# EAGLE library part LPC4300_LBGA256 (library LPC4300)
LBGA256 - SOT740-2 LBGA256: plastic low profile ball grid array package; 256 balls grid 1 * 1 mm; body 17 * 17 mm; Solderland 0.45 mm diameter
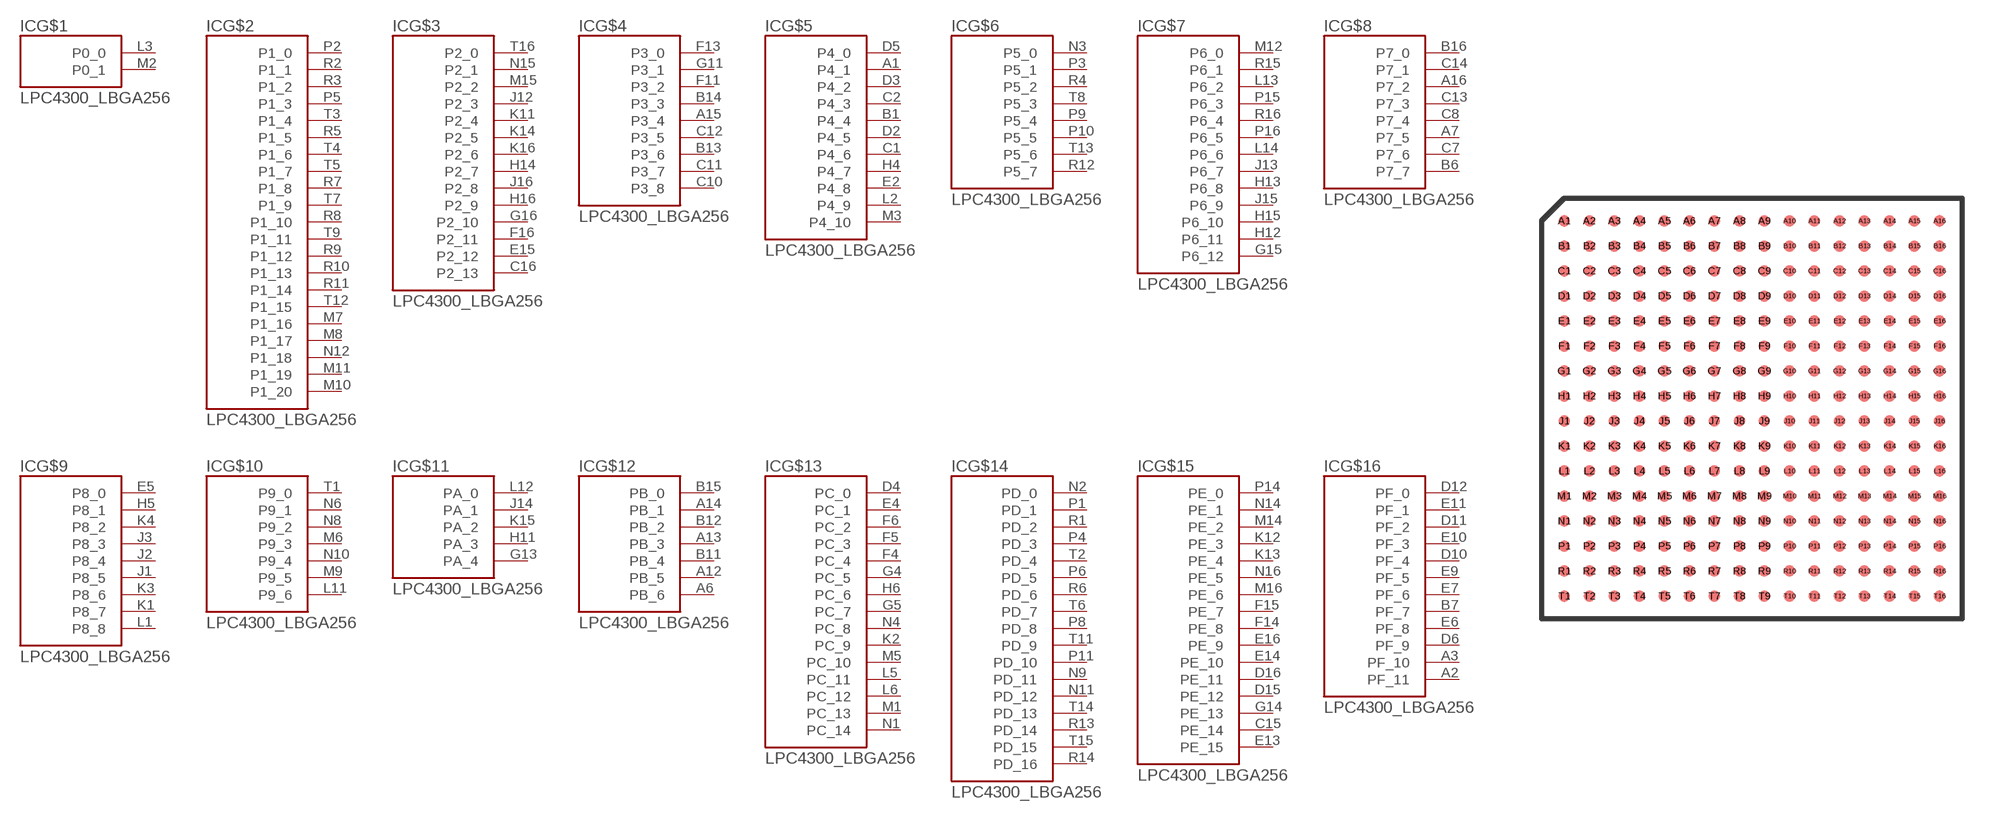
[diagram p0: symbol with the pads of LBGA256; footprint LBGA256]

Designator prefix IC; gates G$1=LPC4300_0_PORT0 G$2=LPC4300_1_PORT1 G$3=LPC4300_2_PORT2 G$4=LPC4300_3_PORT3 G$5=LPC4300_4_PORT4 G$6=LPC4300_5_PORT5 G$7=LPC4300_6_PORT6 G$8=LPC4300_7_PORT7 G$9=LPC4300_8_PORT8 G$10=LPC4300_9_PORT9 G$11=LPC4300_10_PORTA G$12=LPC4300_11_PORTB G$13=LPC4300_12_PORTC G$14=LPC4300_13_PORTD G$15=LPC4300_14_PORTE G$16=LPC4300_15_PORTF G$17=LPC4300_16_ANA G$18=LPC4300_17_RTC G$19=LPC4300_18_CLK G$20=LPC4300_19_DBUG G$21=LPC4300_21_SUP G$22=LPC4300_22_USB G$23=LPC4300_20_I2C

## LPC4300_LBGA256  [LBGA256]
A1  G$5:P4_1
A2  G$16:PF_11
A3  G$16:PF_10
A4  G$17:ADC2  in
A5  G$17:ADC6  in
A6  G$12:PB_6
A7  G$8:P7_5
A8  G$18:RTCX1  in
A9  G$18:WAKEUP0  in
A10  G$18:WAKEUP1  in
A11  G$18:RTC_ALARM  out
A12  G$12:PB_5
A13  G$12:PB_3
A14  G$12:PB_1
A15  G$4:P3_4
A16  G$8:P7_2
B1  G$5:P4_4
B2  G$17:VSSA  sup
B3  G$17:ADC5  in
B4  G$17:VDDA  sup
B5  G$17:ADC3  in
B6  G$8:P7_7
B7  G$16:PF_7
B8  G$18:RTCX2  out
B9  G$18:!SAMPLE  out
B10  G$18:VBAT  pwr
B11  G$12:PB_4
B12  G$12:PB_2
B13  G$4:P3_6
B14  G$4:P3_3
B15  G$12:PB_0
B16  G$8:P7_0
C1  G$5:P4_6
C2  G$5:P4_3
C3  G$17:ADC1  in
C4  G$21:VSSIO1  sup
C5  G$17:ADC7  in
C6  G$17:ADC4  in
C7  G$8:P7_6
C8  G$8:P7_4
C9  G$18:WAKEUP2  in
C10  G$4:P3_8
C11  G$4:P3_7
C12  G$4:P3_5
C13  G$8:P7_3
C14  G$8:P7_1
C15  G$15:PE_14
C16  G$3:P2_13
D1  G$19:XTAL1  in
D2  G$5:P4_5
D3  G$5:P4_2
D4  G$13:PC_0
D5  G$5:P4_0
D6  G$16:PF_9
D7  G$21:VDDIO1  sup
D8  G$18:WAKEUP3  in
D9  G$19:!RESET  in
D10  G$16:PF_4
D11  G$16:PF_2
D12  G$16:PF_0
D13  G$21:VSSIO2  sup
D14  G$19:CLK2  out
D15  G$15:PE_12
D16  G$15:PE_11
E1  G$19:XTAL2  out
E2  G$5:P4_8
E3  G$17:ADC0  in
E4  G$13:PC_1
E5  G$9:P8_0
E6  G$16:PF_8
E7  G$16:PF_6
E8  G$21:VPP  sup
E9  G$16:PF_5
E10  G$16:PF_3
E11  G$16:PF_1
E12  G$21:VDDIO2  sup
E13  G$15:PE_15
E14  G$15:PE_10
E15  G$3:P2_12
E16  G$15:PE_9
F1  G$22:USB0_VBUS
F2  G$22:USB0_DP
F3  G$22:USB0_VDDA3V3_DRIVER
F4  G$13:PC_4
F5  G$13:PC_3
F6  G$13:PC_2
F7  G$21:VDDIO3  sup
F8  G$21:VDDIO4  sup
F9  G$21:VDDREG1  sup
F10  G$21:VDDREG2  sup
F11  G$4:P3_2
F12  G$22:USB1_DP
F13  G$4:P3_0
F14  G$15:PE_8
F15  G$15:PE_7
F16  G$3:P2_11
G1  G$22:USB0_VSSA_REF
G2  G$22:USB0_DM
G3  G$22:USB0_VDDA3V3
G4  G$13:PC_5
G5  G$13:PC_7
G6  G$21:VSSIO3  sup
G7  G$21:VSSIO4  sup
G8  G$21:VSSIO5  sup
G9  G$21:VSS1  sup
G10  G$21:VDDIO5  sup
G11  G$4:P3_1
G12  G$22:USB1_DM
G13  G$11:PA_4
G14  G$15:PE_13
G15  G$7:P6_12
G16  G$3:P2_10
H1  G$22:USB0_RREF
H2  G$22:USB0_ID
H3  G$22:USB0_VSSA_TERM
H4  G$5:P4_7
H5  G$9:P8_1
H6  G$13:PC_6
H7  G$21:VSS2  sup
H8  G$21:VSSIO6  sup
H9  G$21:VSSIO7  sup
H10  G$21:VDDIO6  sup
H11  G$11:PA_3
H12  G$7:P6_11
H13  G$7:P6_8
H14  G$3:P2_7
H15  G$7:P6_10
H16  G$3:P2_9
J1  G$9:P8_5
J2  G$9:P8_4
J3  G$9:P8_3
J4  G$20:TDI
J5  G$20:TCK
J6  G$21:VDDIO7  sup
J7  G$21:VDDIO8  sup
J8  G$21:VSSIO8  sup
J9  G$21:VSSIO9  sup
J10  G$21:VSS3  sup
J11  G$21:VSS4  sup
J12  G$3:P2_3
J13  G$7:P6_7
J14  G$11:PA_1
J15  G$7:P6_9
J16  G$3:P2_8
K1  G$9:P8_7
K2  G$13:PC_9
K3  G$9:P8_6
K4  G$9:P8_2
K5  G$20:TDO
K6  G$20:TMS
K7  G$21:VDDIO9  sup
K8  G$21:VSS5  sup
K9  G$21:VSSIO10  sup
K10  G$21:VSSIO11  sup
K11  G$3:P2_4
K12  G$15:PE_3
K13  G$15:PE_4
K14  G$3:P2_5
K15  G$11:PA_2
K16  G$3:P2_6
L1  G$9:P8_8  sup
L2  G$5:P4_9
L3  G$1:P0_0
L4  G$20:DBGEN  in
L5  G$13:PC_11
L6  G$13:PC_12
L7  G$21:VDDREG4  sup
L8  G$21:VDDREG3  sup
L9  G$21:VDDIO10  sup
L10  G$21:VDDIO11  sup
L11  G$10:P9_6
L12  G$11:PA_0
L13  G$7:P6_2
L14  G$7:P6_6
L15  G$23:I2C0_SCL
L16  G$23:I2C0_SDA
M1  G$13:PC_13
M2  G$1:P0_1
M3  G$5:P4_10
M4  G$20:!TRST
M5  G$13:PC_10
M6  G$10:P9_3
M7  G$2:P1_16
M8  G$2:P1_17
M9  G$10:P9_5
M10  G$2:P1_20
M11  G$2:P1_19
M12  G$7:P6_0
M13  G$21:VSSIO12  sup
M14  G$15:PE_2
M15  G$3:P2_2
M16  G$15:PE_6
N1  G$13:PC_14
N2  G$14:PD_0
N3  G$6:P5_0
N4  G$13:PC_8
N5  G$19:CLK0  out
N6  G$10:P9_1
N7  G$21:VDDIO12  sup
N8  G$10:P9_2
N9  G$14:PD_11
N10  G$10:P9_4
N11  G$14:PD_12
N12  G$2:P1_18
N13  G$21:VDDIO13  sup
N14  G$15:PE_1
N15  G$3:P2_1
N16  G$15:PE_5
P1  G$14:PD_1
P2  G$2:P1_0
P3  G$6:P5_1
P4  G$14:PD_3
P5  G$2:P1_3
P6  G$14:PD_5
P7  G$21:VSSIO13  sup
P8  G$14:PD_8
P9  G$6:P5_4
P10  G$6:P5_5
P11  G$14:PD_10
P12  G$19:CLK3  out
P13  G$21:VSSIO14  sup
P14  G$15:PE_0
P15  G$7:P6_3
P16  G$7:P6_5
R1  G$14:PD_2
R2  G$2:P1_1
R3  G$2:P1_2
R4  G$6:P5_2
R5  G$2:P1_5
R6  G$14:PD_6
R7  G$2:P1_8
R8  G$2:P1_10
R9  G$2:P1_12
R10  G$2:P1_13
R11  G$2:P1_14
R12  G$6:P5_7
R13  G$14:PD_14
R14  G$14:PD_16
R15  G$7:P6_1
R16  G$7:P6_4
T1  G$10:P9_0
T2  G$14:PD_4
T3  G$2:P1_4
T4  G$2:P1_6
T5  G$2:P1_7
T6  G$14:PD_7
T7  G$2:P1_9
T8  G$6:P5_3
T9  G$2:P1_11
T10  G$19:CLK1  out
T11  G$14:PD_9
T12  G$2:P1_15
T13  G$6:P5_6
T14  G$14:PD_13
T15  G$14:PD_15
T16  G$3:P2_0

## Footprint LBGA256 (pad centres in mm)
LBGA256 - SOT740-2 LBGA256: plastic low profile ball grid array package; 256 balls; grid 1 x 1 mm; body 17 x 17 mm; Solderland 0.45 mm diameter
smd 0.45 x 0.45: A1 -7.5,7.5; A2 -6.5,7.5; A3 -5.5,7.5; A4 -4.5,7.5; A5 -3.5,7.5; A6 -2.5,7.5; A7 -1.5,7.5; A8 -0.5,7.5; A9 0.5,7.5; A10 1.5,7.5; A11 2.5,7.5; A12 3.5,7.5; A13 4.5,7.5; A14 5.5,7.5; A15 6.5,7.5; A16 7.5,7.5; B1 -7.5,6.5; B2 -6.5,6.5; B3 -5.5,6.5; B4 -4.5,6.5; B5 -3.5,6.5; B6 -2.5,6.5; B7 -1.5,6.5; B8 -0.5,6.5; B9 0.5,6.5; B10 1.5,6.5; B11 2.5,6.5; B12 3.5,6.5; B13 4.5,6.5; B14 5.5,6.5; B15 6.5,6.5; B16 7.5,6.5; C1 -7.5,5.5; C2 -6.5,5.5; C3 -5.5,5.5; C4 -4.5,5.5; C5 -3.5,5.5; C6 -2.5,5.5; C7 -1.5,5.5; C8 -0.5,5.5; C9 0.5,5.5; C10 1.5,5.5; C11 2.5,5.5; C12 3.5,5.5; C13 4.5,5.5; C14 5.5,5.5; C15 6.5,5.5; C16 7.5,5.5; D1 -7.5,4.5; D2 -6.5,4.5; D3 -5.5,4.5; D4 -4.5,4.5; D5 -3.5,4.5; D6 -2.5,4.5; D7 -1.5,4.5; D8 -0.5,4.5; D9 0.5,4.5; D10 1.5,4.5; D11 2.5,4.5; D12 3.5,4.5; D13 4.5,4.5; D14 5.5,4.5; D15 6.5,4.5; D16 7.5,4.5; E1 -7.5,3.5; E2 -6.5,3.5; E3 -5.5,3.5; E4 -4.5,3.5; E5 -3.5,3.5; E6 -2.5,3.5; E7 -1.5,3.5; E8 -0.5,3.5; E9 0.5,3.5; E10 1.5,3.5; E11 2.5,3.5; E12 3.5,3.5; E13 4.5,3.5; E14 5.5,3.5; E15 6.5,3.5; E16 7.5,3.5; F1 -7.5,2.5; F2 -6.5,2.5; F3 -5.5,2.5; F4 -4.5,2.5; F5 -3.5,2.5; F6 -2.5,2.5; F7 -1.5,2.5; F8 -0.5,2.5; F9 0.5,2.5; F10 1.5,2.5; F11 2.5,2.5; F12 3.5,2.5; F13 4.5,2.5; F14 5.5,2.5; F15 6.5,2.5; F16 7.5,2.5; G1 -7.5,1.5; G2 -6.5,1.5; G3 -5.5,1.5; G4 -4.5,1.5; G5 -3.5,1.5; G6 -2.5,1.5; G7 -1.5,1.5; G8 -0.5,1.5; G9 0.5,1.5; G10 1.5,1.5; G11 2.5,1.5; G12 3.5,1.5; G13 4.5,1.5; G14 5.5,1.5; G15 6.5,1.5; G16 7.5,1.5; H1 -7.5,0.5; H2 -6.5,0.5; H3 -5.5,0.5; H4 -4.5,0.5; H5 -3.5,0.5; H6 -2.5,0.5; H7 -1.5,0.5; H8 -0.5,0.5; H9 0.5,0.5; H10 1.5,0.5; H11 2.5,0.5; H12 3.5,0.5; H13 4.5,0.5; H14 5.5,0.5; H15 6.5,0.5; H16 7.5,0.5; J1 -7.5,-0.5; J2 -6.5,-0.5; J3 -5.5,-0.5; J4 -4.5,-0.5; J5 -3.5,-0.5; J6 -2.5,-0.5; J7 -1.5,-0.5; J8 -0.5,-0.5; J9 0.5,-0.5; J10 1.5,-0.5; J11 2.5,-0.5; J12 3.5,-0.5; J13 4.5,-0.5; J14 5.5,-0.5; J15 6.5,-0.5; J16 7.5,-0.5; K1 -7.5,-1.5; K2 -6.5,-1.5; K3 -5.5,-1.5; K4 -4.5,-1.5; K5 -3.5,-1.5; K6 -2.5,-1.5; K7 -1.5,-1.5; K8 -0.5,-1.5; K9 0.5,-1.5; K10 1.5,-1.5; K11 2.5,-1.5; K12 3.5,-1.5; K13 4.5,-1.5; K14 5.5,-1.5; K15 6.5,-1.5; K16 7.5,-1.5; L1 -7.5,-2.5; L2 -6.5,-2.5; L3 -5.5,-2.5; L4 -4.5,-2.5; L5 -3.5,-2.5; L6 -2.5,-2.5; L7 -1.5,-2.5; L8 -0.5,-2.5; L9 0.5,-2.5; L10 1.5,-2.5; L11 2.5,-2.5; L12 3.5,-2.5; L13 4.5,-2.5; L14 5.5,-2.5; L15 6.5,-2.5; L16 7.5,-2.5; M1 -7.5,-3.5; M2 -6.5,-3.5; M3 -5.5,-3.5; M4 -4.5,-3.5; M5 -3.5,-3.5; M6 -2.5,-3.5; M7 -1.5,-3.5; M8 -0.5,-3.5; M9 0.5,-3.5; M10 1.5,-3.5; M11 2.5,-3.5; M12 3.5,-3.5; M13 4.5,-3.5; M14 5.5,-3.5; M15 6.5,-3.5; M16 7.5,-3.5; N1 -7.5,-4.5; N2 -6.5,-4.5; N3 -5.5,-4.5; N4 -4.5,-4.5; N5 -3.5,-4.5; N6 -2.5,-4.5; N7 -1.5,-4.5; N8 -0.5,-4.5; N9 0.5,-4.5; N10 1.5,-4.5; N11 2.5,-4.5; N12 3.5,-4.5; N13 4.5,-4.5; N14 5.5,-4.5; N15 6.5,-4.5; N16 7.5,-4.5; P1 -7.5,-5.5; P2 -6.5,-5.5; P3 -5.5,-5.5; P4 -4.5,-5.5; P5 -3.5,-5.5; P6 -2.5,-5.5; P7 -1.5,-5.5; P8 -0.5,-5.5; P9 0.5,-5.5; P10 1.5,-5.5; P11 2.5,-5.5; P12 3.5,-5.5; P13 4.5,-5.5; P14 5.5,-5.5; P15 6.5,-5.5; P16 7.5,-5.5; R1 -7.5,-6.5; R2 -6.5,-6.5; R3 -5.5,-6.5; R4 -4.5,-6.5; R5 -3.5,-6.5; R6 -2.5,-6.5; R7 -1.5,-6.5; R8 -0.5,-6.5; R9 0.5,-6.5; R10 1.5,-6.5; R11 2.5,-6.5; R12 3.5,-6.5; R13 4.5,-6.5; R14 5.5,-6.5; R15 6.5,-6.5; R16 7.5,-6.5; T1 -7.5,-7.5; T2 -6.5,-7.5; T3 -5.5,-7.5; T4 -4.5,-7.5; T5 -3.5,-7.5; T6 -2.5,-7.5; T7 -1.5,-7.5; T8 -0.5,-7.5; T9 0.5,-7.5; T10 1.5,-7.5; T11 2.5,-7.5; T12 3.5,-7.5; T13 4.5,-7.5; T14 5.5,-7.5; T15 6.5,-7.5; T16 7.5,-7.5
